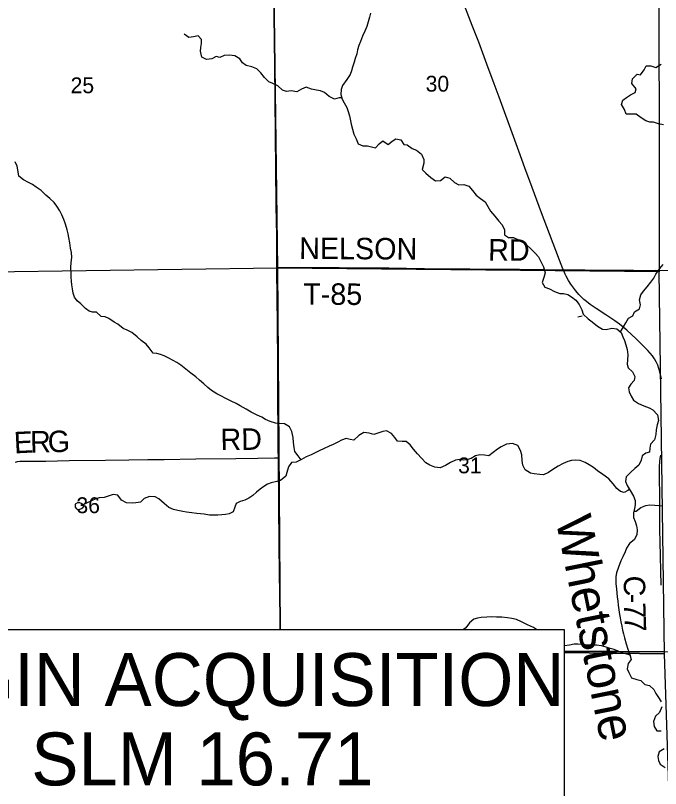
# Model space of a CAD drawing. Extents: x 0 to 34, y 0 to 22.
# Drawn here: x 4.763 to 6.47, y 17.915 to 19.961 of the extents above; entities that cross this region are included whole.
import ezdxf

# ---------------------------------------------------------------- set-up
doc = ezdxf.new("R2010")
doc.units = 0
for name, color, linetype in [('Default', 7, 'Continuous'), ('GM_X_County_Road', 7, 'Continuous'), ('GM_X_County_Road_Text', 7, 'Continuous'), ('GM_X_Minor_Lake', 7, 'Continuous'), ('GM_X_Minor_River', 7, 'Continuous'), ('GM_X_Minor_River_Text', 7, 'Continuous'), ('GM_X_Section', 7, 'Continuous'), ('GM_X_Section_Text', 7, 'Continuous'), ('GM_X_Township_Road', 7, 'Continuous'), ('GM_X_Township_Road_Text', 7, 'Continuous')]:
    doc.layers.add(name, color=color, linetype=linetype)

msp = doc.modelspace()

# ---------------------------------------------------------------- linework, layer by layer
at = {"layer": 'Default'}
for points in [[(4.3145, 18.3355), (6.2148, 18.3355), (6.2148, 18.2783), (6.4787, 18.2762)], [(7.5053, 17.3084), (7.5051, 18.039), (7.5056, 18.0926), (7.5011, 18.2616), (7.4731, 18.2617), (6.4787, 18.2762), (6.2148, 18.2783), (6.2148, 17.662)]]:
    msp.add_lwpolyline(points, dxfattribs=at)
at = {"layer": 'GM_X_County_Road'}
for points in [[(6.2126, 19.2872), (6.2113, 19.2901), (6.2022, 19.3132), (6.1758, 19.3829), (6.1551, 19.4382), (6.1301, 19.5051), (6.1108, 19.5577), (6.0947, 19.6013), (6.0841, 19.6304), (6.0427, 19.7443), (6.0297, 19.7793), (6.0102, 19.8317), (5.9885, 19.8895), (5.9716, 19.9341), (5.9425, 20.0105), (5.9236, 20.0598), (5.9093, 20.0976), (5.883, 20.1674), (5.851, 20.2516), (5.8383, 20.2834), (5.8306, 20.3012)], [(6.472, 18.999), (6.4682, 19.0173), (6.4657, 19.0263), (6.4625, 19.0352), (6.4584, 19.0436), (6.4537, 19.0518), (6.4484, 19.0595), (6.4426, 19.0669), (6.4363, 19.0738), (6.4254, 19.0849), (6.4053, 19.1044), (6.3803, 19.1278), (6.371, 19.136), (6.3612, 19.1437), (6.3485, 19.1527), (6.3251, 19.1681), (6.2991, 19.1852), (6.2838, 19.1958), (6.274, 19.2033), (6.2669, 19.2092), (6.2601, 19.2156), (6.2537, 19.2223), (6.2456, 19.2317), (6.2399, 19.239), (6.2327, 19.2491), (6.2261, 19.2596), (6.2201, 19.2704), (6.2175, 19.2759), (6.2126, 19.2872)], [(6.4711, 18.453), (6.4684, 18.568), (6.4681, 18.5991), (6.4678, 18.6239), (6.4675, 18.6798), (6.4667, 18.7481), (6.4668, 18.7667), (6.4676, 18.779), (6.4688, 18.7882), (6.4705, 18.7973)]]:
    msp.add_lwpolyline(points, dxfattribs=at)
at = {"layer": 'GM_X_Minor_Lake'}
for points in [[(4.9416, 18.6649), (4.939, 18.6684), (4.9329, 18.6707), (4.9265, 18.6707), (4.9204, 18.6669), (4.9211, 18.6593), (4.9245, 18.6548), (4.9291, 18.6521), (4.9313, 18.6528), (4.9374, 18.6562)], [(4.9374, 18.6562), (4.9414, 18.6586), (4.9428, 18.6598), (4.9428, 18.661), (4.9416, 18.6649)]]:
    msp.add_lwpolyline(points, dxfattribs=at)
at = {"layer": 'GM_X_Minor_River'}
for points in [[(5.7022, 19.9662), (5.6999, 19.9563), (5.6961, 19.9434), (5.6926, 19.9317), (5.6876, 19.9192), (5.6811, 19.9059), (5.6757, 19.8919), (5.6718, 19.8813), (5.668, 19.8692), (5.6657, 19.8593), (5.6618, 19.8468), (5.6587, 19.8366), (5.6549, 19.8237), (5.6522, 19.8142), (5.6487, 19.8044), (5.6392, 19.7915), (5.6285, 19.7748), (5.6246, 19.7646), (5.6234, 19.7517), (5.6271, 19.7388), (5.6328, 19.7293), (5.6396, 19.7171), (5.6433, 19.7068), (5.6463, 19.6951), (5.6489, 19.6821), (5.6511, 19.6726), (5.6545, 19.6593), (5.6582, 19.6468), (5.6642, 19.6339), (5.6698, 19.6209), (5.6823, 19.6152), (5.6945, 19.6155), (5.7051, 19.6128)], [(5.6261, 19.7424), (5.6192, 19.7423), (5.6067, 19.7389), (5.593, 19.7462), (5.5809, 19.7565), (5.5703, 19.7611), (5.5593, 19.7627), (5.5457, 19.7658), (5.5317, 19.7704), (5.5195, 19.7659), (5.507, 19.7584), (5.4922, 19.7607), (5.4796, 19.7589), (5.4698, 19.7631), (5.4566, 19.7742), (5.4437, 19.7807), (5.4331, 19.7853), (5.4214, 19.7967), (5.412, 19.8086), (5.401, 19.8196), (5.3881, 19.825), (5.3733, 19.8277), (5.3635, 19.8354), (5.3567, 19.846), (5.3431, 19.8533), (5.3291, 19.8553), (5.3154, 19.8542), (5.3036, 19.8497), (5.2934, 19.8516), (5.2827, 19.8456), (5.2679, 19.8442), (5.2562, 19.8503), (5.2525, 19.8659), (5.2533, 19.8754), (5.2552, 19.886), (5.2553, 19.8966), (5.2466, 19.9065), (5.2337, 19.9036), (5.2216, 19.9025), (5.2087, 19.9109)], [(6.4775, 19.6709), (6.4643, 19.6736), (6.451, 19.6778), (6.4411, 19.6779), (6.4309, 19.6817), (6.4184, 19.6898), (6.4056, 19.6993), (6.3915, 19.699), (6.3786, 19.6994), (6.3741, 19.712), (6.3666, 19.7249), (6.3697, 19.7367), (6.38, 19.7438), (6.3899, 19.7502), (6.4024, 19.757), (6.4055, 19.7665), (6.3938, 19.7802), (6.3954, 19.7931), (6.4076, 19.8048), (6.4171, 19.8036), (6.4263, 19.8165), (6.432, 19.8275), (6.4445, 19.827), (6.457, 19.8232), (6.4711, 19.8318)], [(5.7051, 19.6128), (5.7153, 19.6101), (5.7256, 19.6207), (5.7351, 19.629), (5.7487, 19.6194), (5.7598, 19.6281), (5.7693, 19.6345), (5.7822, 19.631), (5.7901, 19.6192), (5.7996, 19.618), (5.8124, 19.6081), (5.8238, 19.6039), (5.8374, 19.5932), (5.8438, 19.5791), (5.843, 19.5696), (5.8387, 19.5533), (5.8489, 19.5434), (5.8618, 19.5319), (5.8746, 19.5231), (5.8875, 19.5238), (5.9001, 19.5333), (5.9126, 19.5298), (5.9243, 19.5183), (5.9364, 19.5126), (5.9493, 19.5129), (5.9622, 19.509), (5.9724, 19.4972), (5.9815, 19.485), (5.9936, 19.4766), (6.0057, 19.4675), (6.0128, 19.4549), (6.02, 19.4431), (6.0313, 19.4294), (6.0422, 19.4164), (6.0509, 19.4061), (6.0569, 19.3932), (6.0565, 19.3803), (6.0674, 19.373), (6.0803, 19.3726), (6.0925, 19.368), (6.1027, 19.363), (6.1163, 19.3531), (6.1261, 19.3431), (6.1382, 19.3313), (6.1469, 19.3214), (6.1496, 19.3169)], [(5.519, 18.785), (5.511, 18.795), (5.5016, 18.8068), (5.4998, 18.8171), (5.4987, 18.8308), (5.4976, 18.8437), (5.4943, 18.86), (5.4879, 18.8722), (5.4743, 18.8795), (5.4614, 18.8807), (5.4507, 18.8815), (5.4371, 18.8865), (5.4246, 18.8918), (5.4148, 18.8972), (5.4027, 18.9026), (5.3868, 18.9106), (5.3728, 18.9183), (5.3576, 18.9279), (5.3466, 18.9336), (5.3338, 18.9397), (5.319, 18.947), (5.3058, 18.9539), (5.2955, 18.9597), (5.2819, 18.9685), (5.2721, 18.9761), (5.2608, 18.9856), (5.2498, 18.9952), (5.24, 19.004), (5.2268, 19.0139), (5.2139, 19.0242), (5.2003, 19.0349), (5.1897, 19.0422), (5.1799, 19.0475), (5.1666, 19.0544), (5.1564, 19.0594), (5.1466, 19.0636), (5.1367, 19.0656), (5.1272, 19.0672), (5.1167, 19.0812), (5.1084, 19.0908), (5.0951, 19.1007), (5.0845, 19.1103), (5.0709, 19.1217), (5.0581, 19.1278), (5.0475, 19.1321), (5.0339, 19.1435), (5.024, 19.1493), (5.01, 19.1588), (5.0002, 19.1627), (4.9892, 19.1635), (4.9767, 19.1753), (4.9669, 19.1757), (4.9574, 19.1777), (4.9476, 19.1853), (4.9355, 19.1975), (4.9256, 19.2052), (4.9185, 19.2154), (4.9155, 19.2261), (4.9136, 19.2367), (4.9118, 19.2477), (4.9107, 19.2572), (4.91, 19.2682), (4.9097, 19.2796), (4.9094, 19.2937), (4.9102, 19.3066), (4.9118, 19.3202), (4.9107, 19.3332), (4.9085, 19.3449), (4.9063, 19.359), (4.9037, 19.373), (4.9018, 19.3825), (4.8996, 19.3936), (4.8951, 19.4084), (4.8906, 19.4206), (4.8858, 19.4327), (4.8805, 19.4434), (4.8718, 19.4563), (4.8647, 19.4658), (4.8537, 19.4758), (4.8431, 19.4853), (4.831, 19.4971), (4.8174, 19.5063), (4.8076, 19.5128), (4.797, 19.5189), (4.7841, 19.5255), (4.772, 19.535), (4.7694, 19.5468), (4.7676, 19.562), (4.762, 19.573)], [(6.1496, 19.3169), (6.1604, 19.2955), (6.1641, 19.2799), (6.161, 19.267), (6.1564, 19.2542), (6.1632, 19.2416), (6.1761, 19.2374), (6.1893, 19.2301), (6.2033, 19.2247), (6.2132, 19.2247), (6.2246, 19.222), (6.2344, 19.2158), (6.2454, 19.207), (6.2544, 19.196), (6.2619, 19.1815), (6.2649, 19.1701), (6.2785, 19.1579), (6.2891, 19.1495), (6.3031, 19.1384), (6.3163, 19.1308), (6.3258, 19.1296), (6.341, 19.1329), (6.3543, 19.1314), (6.3656, 19.1218), (6.3697, 19.11), (6.3742, 19.1001), (6.378, 19.0887), (6.3813, 19.0762), (6.3828, 19.0621), (6.382, 19.0496), (6.3812, 19.0382), (6.3838, 19.0283), (6.3958, 19.0177), (6.4015, 19.0055), (6.4003, 18.9945), (6.3911, 18.9847), (6.385, 18.9748), (6.3869, 18.9649), (6.3925, 18.9531), (6.3981, 18.9429), (6.4118, 18.9333), (6.4258, 18.9279), (6.4394, 18.9218), (6.4496, 18.9168), (6.4617, 18.9038), (6.4643, 18.8886), (6.4608, 18.8773), (6.4581, 18.8644), (6.4573, 18.8515), (6.4542, 18.8375), (6.4435, 18.8257), (6.4412, 18.8159), (6.4407, 18.8045), (6.4305, 18.8023), (6.421, 18.7955), (6.4183, 18.7841), (6.4121, 18.7709), (6.4022, 18.7618), (6.3912, 18.7524), (6.379, 18.7399), (6.377, 18.727), (6.3815, 18.7163), (6.3894, 18.7038), (6.3984, 18.6886), (6.4029, 18.6768), (6.4025, 18.6658), (6.4006, 18.6555), (6.3978, 18.6441), (6.3986, 18.6324), (6.4027, 18.6213), (6.406, 18.6099), (6.4079, 18.5997), (6.4071, 18.5864), (6.4002, 18.5728), (6.3876, 18.563), (6.3799, 18.5512), (6.3761, 18.541), (6.3703, 18.5277), (6.365, 18.5171), (6.3581, 18.5009), (6.3535, 18.4857), (6.3519, 18.4762), (6.3511, 18.466), (6.3514, 18.4565), (6.3529, 18.4436), (6.354, 18.4322), (6.3554, 18.4223), (6.3565, 18.4105), (6.358, 18.4003), (6.3594, 18.3881), (6.3613, 18.3756), (6.3631, 18.3661), (6.3646, 18.3562), (6.3672, 18.3448), (6.369, 18.3338), (6.3717, 18.3243), (6.3743, 18.3136), (6.3784, 18.2981), (6.3828, 18.284), (6.3885, 18.2699), (6.3918, 18.2562)], [(6.3638, 19.1234), (6.3721, 19.137), (6.3783, 19.1472), (6.3848, 19.1597), (6.3966, 19.1661), (6.4012, 19.1763), (6.4137, 19.1846), (6.4172, 19.1944), (6.4142, 19.2081), (6.4173, 19.221), (6.4246, 19.2312), (6.4345, 19.2426), (6.4444, 19.255), (6.4517, 19.2656), (6.4574, 19.2762), (6.4681, 19.2906), (6.4765, 19.3012)], [(6.2622, 19.1648), (6.2512, 19.1626)], [(6.3879, 18.7062), (6.383, 18.7031), (6.3734, 18.6985), (6.364, 18.7005), (6.3538, 18.7085), (6.344, 18.7215), (6.3326, 18.7344), (6.3171, 18.7455), (6.3031, 18.7558), (6.2922, 18.7642), (6.2808, 18.7715), (6.2699, 18.7772), (6.2574, 18.7826), (6.2441, 18.7838), (6.2346, 18.7827), (6.2243, 18.7801), (6.2118, 18.7749), (6.1992, 18.7677), (6.1851, 18.7587), (6.1737, 18.7511), (6.16, 18.7451), (6.1506, 18.7459), (6.1358, 18.7479), (6.1259, 18.7495), (6.1119, 18.7579), (6.1051, 18.7701), (6.1037, 18.783), (6.1026, 18.7982), (6.0993, 18.8096), (6.0921, 18.8225), (6.0781, 18.8279), (6.0618, 18.8257), (6.0477, 18.8189), (6.0382, 18.8129), (6.0268, 18.8042), (6.0153, 18.7948), (6.0043, 18.7968), (5.9914, 18.7983), (5.98, 18.795), (5.9682, 18.7886), (5.9587, 18.7852), (5.9492, 18.7838), (5.9375, 18.7857), (5.9272, 18.7835), (5.9143, 18.7775), (5.9006, 18.7696), (5.8862, 18.7636), (5.8729, 18.7651), (5.8593, 18.7702), (5.8487, 18.777), (5.837, 18.7892), (5.8268, 18.8003), (5.8158, 18.8125), (5.8075, 18.8243), (5.7966, 18.8335), (5.7863, 18.8331), (5.7738, 18.834), (5.7666, 18.8439), (5.7576, 18.8542), (5.7443, 18.8611), (5.7345, 18.8596), (5.7246, 18.8562), (5.7109, 18.8517), (5.6988, 18.8556), (5.6847, 18.8572), (5.6718, 18.8493), (5.6577, 18.8364), (5.6482, 18.8387), (5.6376, 18.8407), (5.6255, 18.8366), (5.6156, 18.8317), (5.6038, 18.8253), (5.5931, 18.8208), (5.5779, 18.8137), (5.5684, 18.8092), (5.5589, 18.8046), (5.5448, 18.7979), (5.5323, 18.7926), (5.5193, 18.7851), (5.5056, 18.7783), (5.4935, 18.7773), (5.4855, 18.7663), (5.4809, 18.7515), (5.4781, 18.7417), (5.4644, 18.7303), (5.4542, 18.727), (5.4397, 18.7236), (5.4295, 18.7199), (5.42, 18.7142), (5.4101, 18.7067), (5.4005, 18.6988), (5.391, 18.6905), (5.3804, 18.6829), (5.3701, 18.678), (5.3572, 18.6747), (5.3465, 18.6694), (5.3431, 18.6592), (5.3384, 18.6467), (5.3286, 18.6418), (5.3187, 18.6399), (5.3088, 18.6389)], [(5.3088, 18.6389), (5.2986, 18.6378), (5.2766, 18.6386), (5.2621, 18.6406), (5.2527, 18.6418), (5.2424, 18.6426), (5.2295, 18.6442), (5.2155, 18.6465), (5.206, 18.6477), (5.1928, 18.6508), (5.1806, 18.6535), (5.1685, 18.6585), (5.156, 18.6692), (5.1424, 18.6814), (5.1326, 18.6864), (5.1174, 18.6872), (5.1037, 18.682), (5.0938, 18.6722), (5.0809, 18.6707), (5.0711, 18.6704), (5.0566, 18.6712), (5.043, 18.6777), (5.034, 18.6907), (5.0215, 18.693), (5.0078, 18.6882), (4.9975, 18.6852), (4.9846, 18.6837), (4.9751, 18.6815), (4.9414, 18.6652)], [(6.3989, 18.6487), (6.4051, 18.649), (6.4177, 18.6589), (6.4313, 18.6641), (6.4408, 18.6652), (6.4545, 18.6644), (6.4651, 18.6636), (6.475, 18.6627)], [(6.1419, 18.3355), (6.1338, 18.3406), (6.1175, 18.3483), (6.1016, 18.356), (6.0888, 18.3617), (6.0759, 18.3648), (6.0652, 18.3664), (6.0501, 18.368), (6.036, 18.3684), (6.0212, 18.3689), (6.0099, 18.3686), (5.9954, 18.3675), (5.9852, 18.366), (5.9753, 18.3634), (5.9643, 18.3532), (5.9543, 18.3404), (5.9482, 18.3355)], [(6.3889, 18.2679), (6.3839, 18.2696), (6.371, 18.273), (6.3578, 18.278), (6.3472, 18.2823), (6.3369, 18.2857), (6.3263, 18.2892), (6.3138, 18.2923), (6.3005, 18.2939), (6.2903, 18.2943), (6.2766, 18.2944), (6.2645, 18.296), (6.2512, 18.2968), (6.241, 18.2965), (6.2292, 18.2946), (6.2155, 18.2924), (6.2148, 18.2924)], [(6.3918, 18.2562), (6.3838, 18.2453), (6.3811, 18.2312), (6.3856, 18.2217), (6.3931, 18.208), (6.4071, 18.2034), (6.4174, 18.2003), (6.4279, 18.1904), (6.4408, 18.1873), (6.4521, 18.1766), (6.4574, 18.1667), (6.4661, 18.1534), (6.4717, 18.1439)], [(6.4728, 18.1306), (6.467, 18.1162), (6.4564, 18.1067), (6.451, 18.0923), (6.4528, 18.0794), (6.46, 18.0676), (6.4717, 18.0676)], [(6.4795, 18.0201), (6.4662, 18.0122), (6.4627, 17.9997), (6.4645, 17.989), (6.4687, 17.9791), (6.4819, 17.9703)]]:
    msp.add_lwpolyline(points, dxfattribs=at)
at = {"layer": 'GM_X_Section'}
for points in [[(5.4429, 20.296), (5.4558, 19.2921), (4.4424, 19.2777), (4.4204, 20.2835)], [(6.4651, 20.2933), (6.4658, 19.2822), (5.4558, 19.2921), (5.4429, 20.296)], [(5.4633, 18.3355), (5.4558, 19.2921), (4.4424, 19.2777), (4.4577, 18.3355)], [(6.2148, 18.2748), (6.4805, 18.2714), (6.4658, 19.2822), (5.4558, 19.2921), (5.4633, 18.3355), (6.2148, 18.3355)], [(5.4402, 17.662), (5.4379, 17.2873), (6.4911, 17.2929), (6.4945, 17.8409), (6.4805, 18.2714), (6.2148, 18.2748), (6.2148, 17.662)]]:
    msp.add_lwpolyline(points, close=True, dxfattribs=at)
at = {"layer": 'GM_X_Township_Road'}
for points in [[(5.4546, 19.294), (5.4543, 19.3063), (5.4545, 19.3498), (5.454, 19.384), (5.4538, 19.412), (5.4528, 19.4617), (5.4492, 19.8287), (5.4491, 19.8827), (5.4487, 19.9138), (5.4486, 19.9387), (5.4479, 19.9728), (5.4474, 20.013), (5.4465, 20.0893), (5.4456, 20.1512), (5.4454, 20.1914), (5.4449, 20.2901), (5.4448, 20.3023)], [(5.4546, 19.294), (5.5424, 19.2937), (5.5924, 19.2935), (5.6197, 19.2933), (5.6489, 19.2931), (5.7055, 19.2927), (5.7508, 19.2924), (5.8451, 19.2912), (5.9137, 19.29), (5.9653, 19.2897), (6.0147, 19.2894), (6.0964, 19.2889), (6.1487, 19.2886), (6.1615, 19.2884), (6.2126, 19.2872)], [(5.4584, 18.79), (5.4581, 18.8122), (5.4577, 18.8712), (5.4569, 18.9334), (5.4569, 19.0016), (5.4567, 19.0482), (5.4555, 19.2224), (5.4547, 19.2783), (5.4546, 19.294)], [(6.2126, 19.2872), (6.2285, 19.2873), (6.2471, 19.2872), (6.2702, 19.287)], [(6.2702, 19.287), (6.3426, 19.2864), (6.3518, 19.2863), (6.3704, 19.2862), (6.3766, 19.2862), (6.3983, 19.2861), (6.4075, 19.286), (6.4262, 19.2858), (6.4355, 19.2858), (6.4572, 19.2862), (6.5685, 19.2858), (6.5965, 19.2858), (6.6307, 19.2852), (6.6547, 19.2848)], [(4.7623, 18.7787), (4.7652, 18.7797), (4.7683, 18.7802), (4.7745, 18.7807), (4.79, 18.7809), (4.8428, 18.7814), (4.9048, 18.7828), (5.001, 18.7839), (5.0631, 18.7847), (5.1128, 18.7852), (5.1562, 18.7858), (5.24, 18.787), (5.3455, 18.7886), (5.4044, 18.7893), (5.4479, 18.7899), (5.4584, 18.79)], [(5.4634, 18.3355), (5.463, 18.3491), (5.4631, 18.3989), (5.4618, 18.4766), (5.4609, 18.5667), (5.4598, 18.6599), (5.4584, 18.79)]]:
    msp.add_lwpolyline(points, dxfattribs=at)

# ---------------------------------------------------------------- texts
at = {"layer": 'Default'}
for s, p in [('BEGIN ACQUISITION', (4.3638, 18.1331)), ('SLM 16.71', (4.8045, 17.9231))]:
    msp.add_text(s, height=0.14, dxfattribs=at).set_placement(p)
at = {"layer": 'GM_X_County_Road_Text'}
for s, rotation, p in [('C', 269.516, (6.3728, 18.4785)), ('-', 271.2886, (6.3724, 18.4299)), ('7', 271.7162, (6.3729, 18.4061)), ('7', 271.8933, (6.374, 18.3709))]:
    msp.add_text(s, height=0.0568, rotation=rotation, dxfattribs=at).set_placement(p)
at = {"layer": 'GM_X_Minor_River_Text'}
msp.add_text('Whetstone', height=0.09474, rotation=281.4771, dxfattribs=at).set_placement((6.1917, 18.6271))
at = {"layer": 'GM_X_Section_Text'}
for s, p in [('25', (4.9086, 19.7548)), ('30', (5.8481, 19.759)), ('31', (5.934, 18.749)), ('36', (4.924, 18.6436))]:
    msp.add_text(s, height=0.04186, rotation=0, dxfattribs=at).set_placement(p)
at = {"layer": 'GM_X_Township_Road_Text'}
for s, height, rotation, p in [('NELSON', 0.05682, 359.6537, (5.5133, 19.3163)), ('RD', 0.05682, 359.5045, (6.0134, 19.3121)), ('T-85', 0.05682, 359.6471, (5.524, 19.1953)), ('G', 0.0568, 1.1257, (4.8485, 18.8045)), ('RD', 0.05682, 0.4937, (5.3054, 18.8104)), ('E', 0.0568, 2.8382, (4.7599, 18.8015)), ('R', 0.0568, 1.1554, (4.8019, 18.8036))]:
    msp.add_text(s, height=height, rotation=rotation, dxfattribs=at).set_placement(p)

doc.saveas('drawing.dxf')
